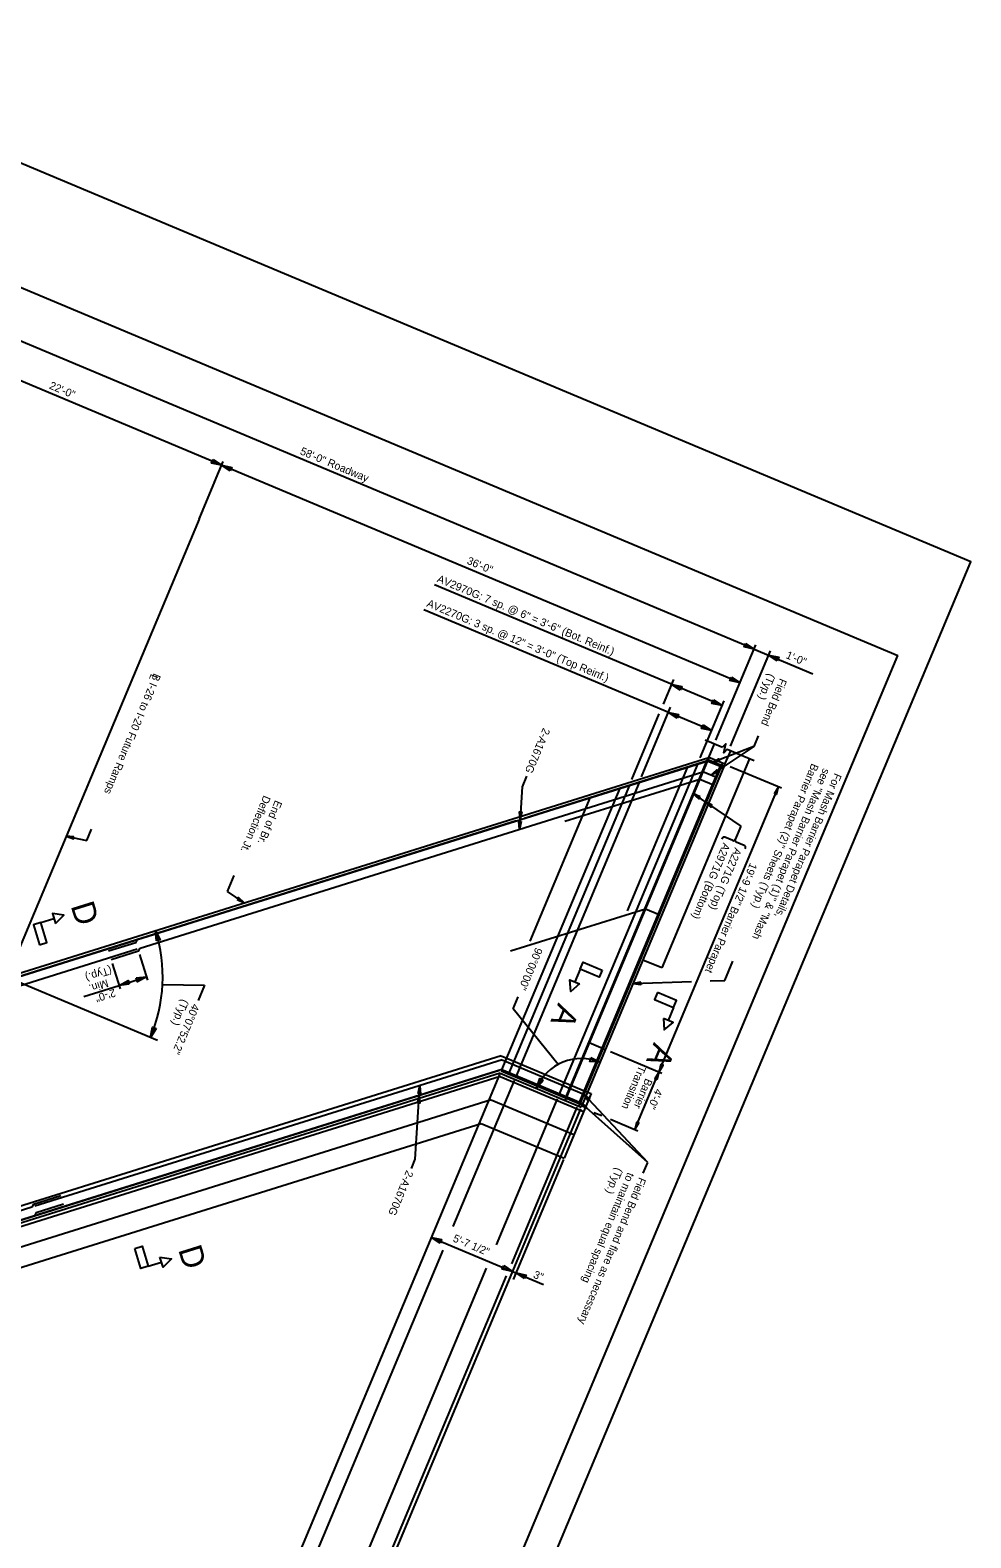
# Model space of a CAD drawing. Extents: x 1968564 to 1968701, y 796599 to 796766.
# Drawn here: x 1968640.5 to 1968700.7, y 796669.3 to 796765.7 of the extents above; entities that cross this region are included whole.
import ezdxf

# ---------------------------------------------------------------- set-up
doc = ezdxf.new("R2010")
doc.units = 0
for name, color, linetype in [('BR_AUTO DIMENSION', 7, 'Continuous'), ('BR_BORDER LINES', 7, 'Continuous'), ('BR_CENTER LINES', 7, 'Continuous'), ('BR_CONCRETE', 7, 'Continuous'), ('BR_DETAILS', 7, 'Continuous'), ('BR_REBAR', 7, 'Continuous'), ('BR_TABLE LINES', 7, 'Continuous'), ('BR_TEXT', 7, 'Continuous'), ('Level 31', 7, 'Continuous')]:
    doc.layers.add(name, color=color, linetype=linetype)

msp = doc.modelspace()

# ---------------------------------------------------------------- linework, layer by layer
at = {"layer": 'BR_AUTO DIMENSION'}
for p, q in [((1968686.819, 796726.134), (1968633.333, 796748.567)), ((1968652.717, 796737.903), (1968632.429, 796746.412)), ((1968652.258, 796736.809), (1968652.814, 796738.134)), ((1968652.258, 796736.809), (1968652.814, 796738.134)), ((1968685.915, 796723.979), (1968652.717, 796737.903)), ((1968651.27, 796734.454), (1968652.281, 796736.864)), ((1968651.27, 796734.454), (1968651.503, 796735.009)), ((1968684.761, 796722.521), (1968666.341, 796730.247)), ((1968684.092, 796720.926), (1968665.672, 796728.652)), ((1968684.371, 796720.298), (1968686.932, 796726.405)), ((1968685.293, 796719.912), (1968687.855, 796726.018)), ((1968686.819, 796726.134), (1968690.576, 796724.558)), ((1968684.371, 796720.298), (1968686.376, 796725.077)), ((1968681.005, 796722.614), (1968681.664, 796724.185)), ((1968683.36, 796719.18), (1968684.891, 796722.831)), ((1968678.977, 796717.78), (1968680.743, 796721.99)), ((1968679.593, 796717.954), (1968681.466, 796722.421)), ((1968686.793, 796719.902), (1968684.043, 796718.06)), ((1968686.793, 796719.902), (1968684.083, 796718.856)), ((1968687.076, 796720.577), (1968686.793, 796719.902)), ((1968672.235, 796717.994), (1968671.952, 796717.319)), ((1968685.275, 796718.627), (1968688.567, 796717.247)), ((1968671.952, 796717.319), (1968671.787, 796714.605)), ((1968679.176, 796695.384), (1968688.378, 796717.326)), ((1968682.898, 796716.894), (1968685.968, 796714.805)), ((1968642.757, 796714.161), (1968644.08, 796713.876)), ((1968644.08, 796713.876), (1968644.389, 796714.613)), ((1968684.767, 796714.024), (1968684.745, 796713.971)), ((1968685.443, 796713.876), (1968684.931, 796714.091)), ((1968685.968, 796714.805), (1968685.607, 796713.943)), ((1968686.186, 796713.564), (1968685.674, 796713.779)), ((1968686.23, 796713.348), (1968686.253, 796713.401)), ((1968653.096, 796710.619), (1968653.527, 796711.647)), ((1968654.166, 796709.891), (1968653.096, 796710.619)), ((1968647.457, 796706.588), (1968647.973, 796704.937)), ((1968684.936, 796704.928), (1968685.455, 796706.166)), ((1968645.708, 796706.008), (1968646.215, 796704.387)), ((1968639.251, 796705.021), (1968648.6, 796701.1)), ((1968643.888, 796703.905), (1968646.145, 796704.611)), ((1968646.145, 796704.611), (1968647.903, 796705.161)), ((1968648.93, 796704.67), (1968651.615, 796704.616)), ((1968651.615, 796704.616), (1968651.206, 796703.639)), ((1968679.06, 796704.727), (1968682.807, 796704.855)), ((1968684.002, 796704.896), (1968684.936, 796704.928)), ((1968671.382, 796703.109), (1968671.701, 796703.869)), ((1968674.258, 796699.554), (1968671.382, 796703.109)), ((1968677.619, 796700.374), (1968680.911, 796698.994)), ((1968670.518, 796698.902), (1968651.312, 796653.111)), ((1968671.44, 796698.515), (1968667.521, 796689.172)), ((1968665.111, 796693.481), (1968665.398, 796698.185)), ((1968680, 796693.273), (1968675.91, 796697.646)), ((1968675.7, 796696.716), (1968656.465, 796650.854)), ((1968674.206, 796697.355), (1968670.287, 796688.011)), ((1968675.47, 796696.813), (1968671.267, 796686.791)), ((1968680, 796693.273), (1968675.688, 796697.118)), ((1968676.553, 796696.484), (1968677.052, 796696.274)), ((1968677.609, 796696.041), (1968679.364, 796695.305)), ((1968664.864, 796692.891), (1968665.111, 796693.481)), ((1968674.606, 796693.459), (1968671.384, 796685.779)), ((1968679.717, 796692.598), (1968680, 796693.273)), ((1968666.148, 796688.483), (1968673.334, 796685.469)), ((1968666.888, 796687.664), (1968651.27, 796650.425)), ((1968669.655, 796686.504), (1968654.729, 796650.915)), ((1968670.942, 796686.017), (1968656.24, 796650.963))]:
    msp.add_line(p, q, dxfattribs=at)
for points in [[(1968652.166, 796738.27), (1968652.717, 796737.903), (1968652.069, 796738.039)], [(1968653.268, 796737.537), (1968652.717, 796737.903), (1968653.365, 796737.767)], [(1968686.268, 796726.501), (1968686.819, 796726.134), (1968686.171, 796726.27)], [(1968688.292, 796725.381), (1968687.741, 796725.747), (1968688.389, 796725.611)], [(1968682.085, 796723.508), (1968681.534, 796723.875), (1968682.181, 796723.738)], [(1968685.364, 796724.346), (1968685.915, 796723.979), (1968685.267, 796724.116)], [(1968684.21, 796722.887), (1968684.761, 796722.521), (1968684.113, 796722.657)], [(1968681.877, 796721.72), (1968681.326, 796722.087), (1968681.974, 796721.95)], [(1968683.541, 796721.293), (1968684.092, 796720.926), (1968683.445, 796721.062)], [(1968684.576, 796718.966), (1968684.083, 796718.856), (1968684.522, 796719.106)], [(1968684.501, 796718.276), (1968684.043, 796718.06), (1968684.417, 796718.4)], [(1968683.354, 796716.675), (1968682.898, 796716.894), (1968683.269, 796716.551)], [(1968688.254, 796716.836), (1968688.378, 796717.326), (1968688.116, 796716.894)], [(1968684.127, 796716.148), (1968683.671, 796716.368), (1968684.043, 796716.024)], [(1968671.892, 796715.099), (1968671.787, 796714.605), (1968671.742, 796715.108)], [(1968671.929, 796715.712), (1968671.824, 796715.217), (1968671.78, 796715.721)], [(1968643.261, 796714.129), (1968642.757, 796714.161), (1968643.23, 796713.982)], [(1968653.71, 796710.111), (1968654.166, 796709.891), (1968653.794, 796710.235)], [(1968648.543, 796707.454), (1968648.486, 796708.114), (1968648.783, 796707.522)], [(1968646.803, 796704.686), (1968646.145, 796704.611), (1968646.728, 796704.924)], [(1968647.245, 796705.086), (1968647.903, 796705.161), (1968647.32, 796704.848)], [(1968679.558, 796704.819), (1968679.06, 796704.727), (1968679.563, 796704.669)], [(1968648.514, 796701.845), (1968648.166, 796701.282), (1968648.281, 796701.934)], [(1968676.358, 796699.991), (1968676.948, 796699.69), (1968676.289, 796699.75)], [(1968680.847, 796699.563), (1968680.723, 796699.073), (1968680.985, 796699.505)], [(1968673.305, 796698.531), (1968672.878, 796698.025), (1968673.087, 796698.653)], [(1968680.599, 796698.583), (1968680.723, 796699.073), (1968680.46, 796698.641)], [(1968665.255, 796697.078), (1968665.36, 796697.572), (1968665.405, 796697.069)], [(1968665.293, 796697.69), (1968665.398, 796698.185), (1968665.442, 796697.681)], [(1968676.306, 796697.332), (1968675.91, 796697.646), (1968676.196, 796697.23)], [(1968676.111, 796696.841), (1968675.688, 796697.118), (1968676.011, 796696.729)], [(1968679.3, 796695.874), (1968679.176, 796695.384), (1968679.438, 796695.816)], [(1968666.699, 796688.117), (1968666.148, 796688.483), (1968666.796, 796688.347)], [(1968670.784, 796686.675), (1968671.335, 796686.308), (1968670.687, 796686.444)], [(1968672.117, 796685.844), (1968671.566, 796686.211), (1968672.213, 796686.075)]]:
    msp.add_lwpolyline(points, close=True, dxfattribs=at)
for centre, radius, start, end in [((1968684.883, 796713.975), 0.125, 67.24601, 157.24601), ((1968685.491, 796713.991), 0.125, 247.24601, 337.24601), ((1968685.722, 796713.894), 0.125, 157.24601, 247.24601), ((1968686.137, 796713.449), 0.125, 337.24601, 67.24601), ((1968638.974, 796705.137), 9.967, 337.24601, 17.37718), ((1968675.745, 796696.823), 3.109, 67.24601, 157.24601)]:
    msp.add_arc(centre, radius, start, end, dxfattribs=at)
at = {"layer": 'BR_BORDER LINES'}
for p in [(1968618.549, 796758.212), (1968643.927, 796601.539)]:
    msp.add_line(p, (1968696.012, 796725.723), dxfattribs=at)
at = {"layer": 'BR_CENTER LINES'}
msp.add_line((1968651.27, 796734.454), (1968628.225, 796679.508), dxfattribs=at)
at = {"layer": 'BR_CONCRETE'}
for p, q in [((1968683.91, 796719.2), (1968684.275, 796720.068)), ((1968629.619, 796702.21), (1968683.91, 796719.2)), ((1968683.91, 796719.2), (1968674.708, 796697.258)), ((1968684.948, 796718.765), (1968675.745, 796696.823)), ((1968686.522, 796719.125), (1968680.904, 796705.729)), ((1968684.948, 796718.765), (1968683.91, 796719.2)), ((1968684.948, 796718.765), (1968685.312, 796719.633)), ((1968680.904, 796705.729), (1968679.693, 796706.236)), ((1968676.255, 796700.947), (1968677.292, 796700.511)), ((1968670.61, 796700.106), (1968604.305, 796679.356)), ((1968670.61, 796700.106), (1968676.148, 796697.783)), ((1968670.547, 796698.777), (1968603.767, 796677.878)), ((1968670.558, 796698.998), (1968603.778, 796678.1)), ((1968670.547, 796698.777), (1968675.895, 796696.534)), ((1968670.558, 796698.998), (1968675.745, 796696.823)), ((1968676.379, 796697.687), (1968674.646, 796693.557)), ((1968676.148, 796697.783), (1968676.379, 796697.687)), ((1968669.976, 796697.288), (1968615.12, 796680.121)), ((1968669.976, 796697.288), (1968675.279, 796695.064)), ((1968602.408, 796674.833), (1968669.344, 796695.781)), ((1968669.344, 796695.781), (1968674.646, 796693.557))]:
    msp.add_line(p, q, dxfattribs=at)
at = {"layer": 'BR_DETAILS'}
for p, q in [((1968683.672, 796720.32), (1968684.786, 796719.853)), ((1968685.086, 796719.728), (1968686.816, 796719.002))]:
    msp.add_line(p, q, dxfattribs=at)
msp.add_lwpolyline([(1968685.086, 796719.728), (1968684.874, 796719.503), (1968684.998, 796720.078), (1968684.786, 796719.853)], dxfattribs=at)
at = {"layer": 'BR_REBAR'}
for p, q in [((1968647.33, 796707.552), (1968683.814, 796718.969)), ((1968683.202, 796718.803), (1968674.311, 796697.605)), ((1968683.808, 796719.062), (1968674.734, 796697.428)), ((1968684.653, 796718.708), (1968675.579, 796697.073)), ((1968684.697, 796718.598), (1968683.814, 796718.969)), ((1968647.501, 796707.004), (1968683.524, 796718.278)), ((1968674.701, 796715.116), (1968683.33, 796717.816)), ((1968678.71, 796709.386), (1968682.578, 796718.608)), ((1968683.33, 796717.816), (1968684.214, 796717.446)), ((1968684.407, 796717.907), (1968683.524, 796718.278)), ((1968678.209, 796717.241), (1968670.642, 796699.199)), ((1968678.833, 796717.436), (1968671.083, 796698.959)), ((1968679.445, 796717.602), (1968671.545, 796698.765)), ((1968672.469, 796707.433), (1968676.337, 796716.655)), ((1968671.22, 796706.816), (1968679.849, 796709.517)), ((1968679.849, 796709.517), (1968680.733, 796709.146)), ((1968629.434, 796701.951), (1968647.133, 796707.49)), ((1968647.22, 796707.343), (1968645.462, 796706.793)), ((1968647.22, 796707.343), (1968647.33, 796707.552)), ((1968629.151, 796701.262), (1968647.305, 796706.943)), ((1968647.392, 796706.796), (1968645.633, 796706.245)), ((1968647.392, 796706.796), (1968647.501, 796707.004)), ((1968670.682, 796699.838), (1968640.756, 796690.473)), ((1968670.682, 796699.838), (1968675.91, 796697.646)), ((1968670.655, 796699.229), (1968640.928, 796689.926)), ((1968670.655, 796699.229), (1968675.688, 796697.118)), ((1968640.661, 796690.618), (1968642.419, 796691.168)), ((1968640.723, 796689.862), (1968603.874, 796678.33)), ((1968640.552, 796690.409), (1968604.164, 796679.022)), ((1968640.661, 796690.618), (1968640.552, 796690.409)), ((1968640.833, 796690.071), (1968640.723, 796689.862)), ((1968640.833, 796690.071), (1968642.591, 796690.621))]:
    msp.add_line(p, q, dxfattribs=at)
at = {"layer": 'BR_TABLE LINES'}
for p, q in [((1968641.132, 796708.636), (1968641.98, 796708.901)), ((1968675.669, 796705.651), (1968675.326, 796704.831)), ((1968681.658, 796703.194), (1968681.314, 796702.374)), ((1968648.016, 796686.639), (1968648.864, 796686.904))]:
    msp.add_line(p, q, dxfattribs=at)
for points in [[(1968642.08, 796708.583), (1968642.616, 796709.1), (1968641.88, 796709.219)], [(1968641.063, 796707.217), (1968641.53, 796707.363), (1968641.132, 796708.636), (1968640.665, 796708.489)], [(1968677.088, 796705.586), (1968676.899, 796705.135), (1968675.669, 796705.651), (1968675.859, 796706.102)], [(1968675.633, 796704.703), (1968675.068, 796704.217), (1968675.018, 796704.96)], [(1968680.617, 796704.161), (1968680.428, 796703.71), (1968681.658, 796703.194), (1968681.847, 796703.645)], [(1968681.006, 796702.503), (1968681.056, 796701.76), (1968681.621, 796702.246)], [(1968647.151, 796687.765), (1968647.617, 796687.911), (1968648.016, 796686.639), (1968647.549, 796686.493)], [(1968648.764, 796687.222), (1968649.5, 796687.103), (1968648.963, 796686.586)]]:
    msp.add_lwpolyline(points, close=True, dxfattribs=at)
at = {"layer": 'Level 31'}
for p, q in [((1968611.513, 796696.543), (1968683.91, 796719.2)), ((1968672.084, 796715.324), (1968683.96, 796719.041)), ((1968684.794, 796718.829), (1968675.591, 796696.887)), ((1968684.883, 796718.611), (1968683.846, 796719.046)), ((1968611.563, 796696.384), (1968671.575, 796715.165)), ((1968670.508, 796699.157), (1968603.728, 796678.259)), ((1968670.622, 796699.152), (1968675.81, 796696.976))]:
    msp.add_line(p, q, dxfattribs=at)
msp.add_lwpolyline([(1968619.541, 796765.748), (1968563.846, 796632.955), (1968644.997, 796598.919), (1968700.693, 796731.712)], close=True, dxfattribs=at)

# ---------------------------------------------------------------- texts
at = {"layer": 'BR_AUTO DIMENSION'}
for s, rotation, p in [('22\'-0"', 337.24601, (1968641.636, 796742.822)), ('58\'-0" Roadway', 337.24601, (1968657.698, 796738.619)), ('36\'-0"', 337.24601, (1968668.379, 796731.606)), ('AV2970G: 7 sp. @ 6" = 3\'-6" (Bot. Reinf.)', 337.24601, (1968666.464, 796730.45)), ('AV2270G: 3 sp. @ 12" = 3\'-0" (Top Reinf.)', 337.24601, (1968665.805, 796728.879)), ('1\'-0"', 337.24601, (1968688.806, 796725.572)), ('19\'-9 1/2" Barrier Parapet', 247.24601, (1968686.567, 796712.487)), ('(Typ.)', 197.37718, (1968645.6, 796705.833)), ('Min.', 197.37718, (1968645.374, 796705.007)), ('2\'-0"', 197.37718, (1968645.84, 796704.398)), ('4\'-0"', 247.24601, (1968680.508, 796698.042)), ('5\'-7 1/2" ', 337.24601, (1968667.48, 796688.24)), ('3"', 337.24601, (1968672.629, 796685.916))]:
    msp.add_text(s, height=0.5, rotation=rotation, dxfattribs=at).set_placement(p)
at = {"layer": 'BR_TEXT'}
for s, height, rotation, p in [('B I-26 to I-20 Future Ramps', 0.49995, 247.24601, (1968648.381, 796724.621)), ('L', 0.5, 247.24601, (1968648.199, 796724.582)), ('(Typ.)', 0.4999, 247.24601, (1968687.732, 796724.608)), ('Field Bend', 0.4999, 247.24601, (1968688.47, 796724.299)), ('2-A1670G', 0.4999, 247.24601, (1968673.307, 796721.128)), ('Barrier Parapet (2)" Sheets (Typ.) ', 0.49995, 247.24601, (1968690.501, 796718.854)), ('see "Mash Barrier Parapet (1)" & "Mash ', 0.49995, 247.24601, (1968691.239, 796718.544)), ('For Mash Barrier Parapet Details,', 0.49995, 247.24601, (1968691.976, 796718.235)), ('Deflection Jt.', 0.49995, 247.24601, (1968655.413, 796716.81)), ('End of Br.', 0.4999, 247.24601, (1968656.151, 796716.501)), ('A2971G (Bottom)', 0.49995, 247.24601, (1968684.835, 796713.774)), ('A2271G (Top)', 0.49995, 247.24601, (1968685.573, 796713.465)), ('D', 1.5, 287.37718, (1968643.037, 796709.704)), ('90%%d00\'00"', 0.5, 247.24601, (1968672.827, 796707.076)), ('(Typ.)', 0.5, 247.24601, (1968650.176, 796703.766)), ('40%%d07\'52.2"', 0.5, 247.24601, (1968650.856, 796703.48)), ('A', 1.5, 247.24601, (1968674.275, 796703.532)), ('A', 1.5, 247.24601, (1968680.4, 796701.005)), ('Transition', 0.4999, 247.24601, (1968679.449, 796699.521)), ('Barrier', 0.4999, 247.24601, (1968679.863, 796698.697)), ('2-A1670G', 0.4999, 247.24601, (1968664.551, 796692.816)), ('to maintain equal spacing', 0.49995, 247.24601, (1968678.715, 796692.675)), ('(Typ.)', 0.4999, 247.24601, (1968677.977, 796692.985)), ('Field Bend and flare as necessary ', 0.49995, 247.24601, (1968679.452, 796692.366)), ('D', 1.5, 287.37718, (1968649.921, 796687.707))]:
    msp.add_text(s, height=height, rotation=rotation, dxfattribs=at).set_placement(p)

doc.saveas('drawing.dxf')
